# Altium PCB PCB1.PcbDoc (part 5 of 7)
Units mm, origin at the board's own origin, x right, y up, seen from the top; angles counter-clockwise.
Board outline 139.9 x 46.81 mm, 2 copper layers (Top Layer, Bottom Layer); 0 components, 100 nets, 100 pads, 0 vias.
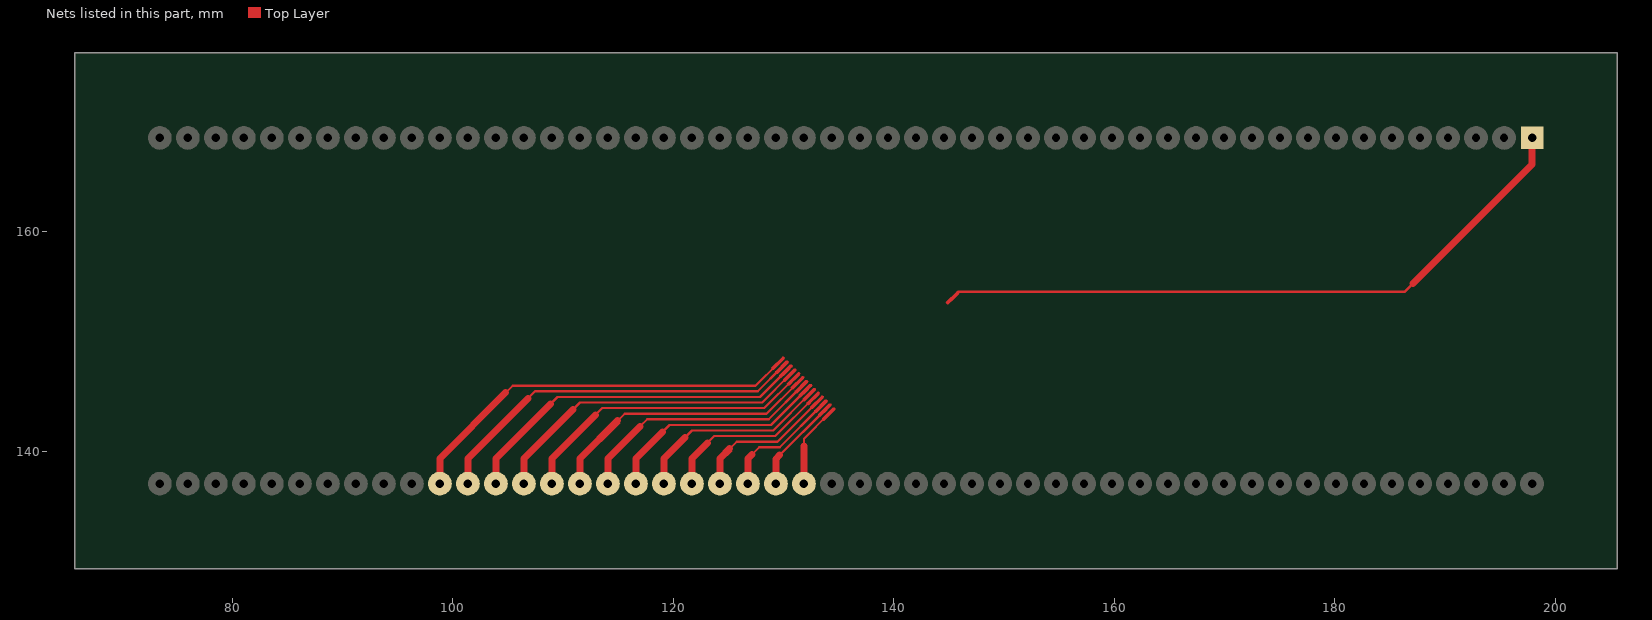
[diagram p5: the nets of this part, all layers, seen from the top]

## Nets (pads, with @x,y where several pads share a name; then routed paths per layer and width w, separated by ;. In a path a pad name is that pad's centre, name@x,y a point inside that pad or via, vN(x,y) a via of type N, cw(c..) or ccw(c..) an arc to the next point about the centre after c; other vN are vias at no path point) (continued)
$Net59: pad.1@197.885,168.455 | length 83.9
  Top Layer w0.03: 144.776,153.497 145.032,153.497 ; 144.776,153.512 145.047,153.512 ; 144.778,153.527 145.063,153.527 ; 144.781,153.481 145.017,153.481 ; 144.788,153.466 145.002,153.466 ; 144.799,153.451 144.987,153.451 ; 144.804,153.573 145.108,153.573 ; 144.811,153.436 144.971,153.436 ; 144.819,153.588 145.124,153.588 ; 144.826,153.42 144.956,153.42 ; 144.834,153.603 145.139,153.603 ; 144.849,153.405 144.938,153.405 ; 144.849,153.619 145.154,153.619 ; 144.865,153.634 145.169,153.634 ; 144.88,153.649 145.185,153.649 ; 144.895,153.664 145.2,153.664 ; 144.91,153.68 145.215,153.68 ; 144.926,153.695 145.23,153.695 ; 144.941,153.71 145.246,153.71 ; 144.956,153.725 145.261,153.725 ; 144.971,153.741 145.276,153.741 ; 144.987,153.756 145.291,153.756 ; 145.002,153.771 145.307,153.771 ; 145.017,153.786 145.322,153.786 ; 145.032,153.801 145.337,153.801 ; 145.047,153.817 145.352,153.817 ; 145.063,153.832 145.368,153.832 ; 145.078,153.542 144.781,153.542 ; 145.078,153.847 145.383,153.847 ; 145.093,153.558 144.788,153.558 ; 145.093,153.862 145.398,153.862 ; 145.108,153.878 145.416,153.878 ; 145.124,153.893 145.431,153.893 ; 145.139,153.908 145.446,153.908 ; 145.154,153.923 145.461,153.923 ; 145.169,153.939 145.477,153.939 ; 145.185,153.954 145.492,153.954 ; 145.2,153.969 145.507,153.969 ; 145.215,153.984 145.522,153.984 ; 145.23,154 145.538,154 ; 145.246,154.015 145.553,154.015 ; 145.261,154.03 145.568,154.03 ; 145.279,154.045 145.583,154.045 ; 145.294,154.061 145.599,154.061 ; 145.309,154.076 145.614,154.076 ; 145.324,154.091 145.629,154.091 ; 145.34,154.106 145.644,154.106 ; 145.355,154.122 145.66,154.122 ; 145.37,154.137 145.675,154.137 ; 145.385,154.152 145.69,154.152 ; 145.401,154.167 145.705,154.167 ; 145.416,154.182 145.721,154.182 ; 145.431,154.198 145.736,154.198 ; 145.446,154.213 145.751,154.213 ; 145.461,154.228 145.766,154.228 ; 145.477,154.243 145.782,154.243 ; 145.492,154.259 145.797,154.259 ; 145.507,154.274 145.812,154.274 ; 145.522,154.289 145.827,154.289 ; 145.538,154.304 145.842,154.304 ; 145.553,154.32 145.858,154.32 ; 145.568,154.335 145.873,154.335 ; 145.583,154.35 145.888,154.35 ; 145.599,154.365 145.898,154.365 ; 145.614,154.381 145.906,154.381 ; 145.629,154.396 145.909,154.396 ; 145.644,154.411 145.911,154.411 ; 145.66,154.426 145.909,154.426 ; 145.675,154.442 145.903,154.442 ; 145.69,154.457 145.893,154.457 ; 145.705,154.472 145.883,154.472 ; 145.721,154.487 145.868,154.487 ; 145.736,154.503 145.853,154.503 ; 145.756,154.518 145.83,154.518 ; 144.781,153.542 144.788,153.558 ; 144.781,153.542 144.773,153.509 144.776,153.492 144.781,153.476 144.801,153.446 144.829,153.418 144.86,153.398 144.875,153.393 144.893,153.39 144.926,153.398 144.938,153.405 ; 144.788,153.558 144.799,153.57 145.746,154.513 145.759,154.52 145.792,154.528 145.809,154.525 145.825,154.52 145.855,154.5 145.883,154.472 ; 144.938,153.405 145.886,154.348 145.896,154.36 145.903,154.376 145.911,154.409 145.909,154.426 ; 145.883,154.472 145.903,154.442 ; 145.903,154.442 145.909,154.426
  Top Layer w0.241: 145.342,153.959 145.868,154.485 186.328,154.485 187.09,155.247
  Top Layer w0.635: 187.09,155.247 187.217,155.374 197.885,166.042 pad.1@197.885,168.455
$Net60: pad.1@98.827,137.086 | length 60.5
  Top Layer w0.03: 128.939,147.556 129.195,147.556 ; 128.939,147.571 129.211,147.571 ; 128.941,147.586 129.226,147.586 ; 128.944,147.54 129.18,147.54 ; 128.951,147.525 129.165,147.525 ; 128.962,147.51 129.15,147.51 ; 128.967,147.632 129.272,147.632 ; 128.974,147.495 129.134,147.495 ; 128.982,147.647 129.287,147.647 ; 128.99,147.479 129.119,147.479 ; 128.997,147.662 129.302,147.662 ; 129.012,147.464 129.101,147.464 ; 129.012,147.678 129.317,147.678 ; 129.028,147.693 129.332,147.693 ; 129.043,147.708 129.348,147.708 ; 129.058,147.723 129.363,147.723 ; 129.073,147.739 129.378,147.739 ; 129.089,147.754 129.393,147.754 ; 129.104,147.769 129.409,147.769 ; 129.119,147.784 129.424,147.784 ; 129.134,147.799 129.439,147.799 ; 129.15,147.815 129.454,147.815 ; 129.165,147.83 129.47,147.83 ; 129.18,147.845 129.485,147.845 ; 129.195,147.86 129.5,147.86 ; 129.211,147.876 129.515,147.876 ; 129.226,147.891 129.531,147.891 ; 129.241,147.601 128.944,147.601 ; 129.241,147.906 129.546,147.906 ; 129.256,147.617 128.951,147.617 ; 129.256,147.921 129.561,147.921 ; 129.272,147.937 129.579,147.937 ; 129.287,147.952 129.594,147.952 ; 129.302,147.967 129.609,147.967 ; 129.317,147.982 129.625,147.982 ; 129.332,147.998 129.64,147.998 ; 129.348,148.013 129.655,148.013 ; 129.363,148.028 129.67,148.028 ; 129.378,148.043 129.686,148.043 ; 129.393,148.059 129.701,148.059 ; 129.409,148.074 129.716,148.074 ; 129.424,148.089 129.731,148.089 ; 129.442,148.104 129.747,148.104 ; 129.457,148.12 129.762,148.12 ; 129.472,148.135 129.777,148.135 ; 129.487,148.15 129.792,148.15 ; 129.503,148.165 129.807,148.165 ; 129.518,148.18 129.823,148.18 ; 129.533,148.196 129.838,148.196 ; 129.548,148.211 129.853,148.211 ; 129.564,148.226 129.868,148.226 ; 129.579,148.241 129.884,148.241 ; 129.594,148.257 129.899,148.257 ; 129.609,148.272 129.914,148.272 ; 129.625,148.287 129.929,148.287 ; 129.64,148.302 129.945,148.302 ; 129.655,148.318 129.96,148.318 ; 129.67,148.333 129.975,148.333 ; 129.686,148.348 129.99,148.348 ; 129.701,148.363 130.006,148.363 ; 129.716,148.379 130.021,148.379 ; 129.731,148.394 130.036,148.394 ; 129.747,148.409 130.051,148.409 ; 129.762,148.424 130.061,148.424 ; 129.777,148.44 130.069,148.44 ; 129.792,148.455 130.072,148.455 ; 129.807,148.47 130.074,148.47 ; 129.823,148.485 130.072,148.485 ; 129.838,148.501 130.067,148.501 ; 129.853,148.516 130.056,148.516 ; 129.868,148.531 130.046,148.531 ; 129.884,148.546 130.031,148.546 ; 129.899,148.561 130.016,148.561 ; 129.919,148.577 129.993,148.577 ; 128.944,147.601 128.951,147.617 ; 128.944,147.601 128.936,147.568 128.939,147.551 128.944,147.535 128.964,147.505 128.992,147.477 129.023,147.457 129.038,147.451 129.056,147.449 129.089,147.457 129.101,147.464 ; 128.951,147.617 128.962,147.629 129.909,148.572 129.922,148.579 129.955,148.587 129.973,148.584 129.988,148.579 130.018,148.559 130.046,148.531 ; 129.101,147.464 130.049,148.407 130.059,148.419 130.067,148.434 130.074,148.467 130.072,148.485 ; 130.046,148.531 130.067,148.501 ; 130.067,148.501 130.072,148.485
  Top Layer w0.203: 104.796,145.341 105.431,145.976 127.461,145.976 129.505,148.018
  Top Layer w0.635: pad.1@98.827,137.086 98.827,139.372 104.796,145.341
$Net61: pad.1@101.367,137.086 | length 58.1
  Top Layer w0.03: 129.292,147.203 129.548,147.203 ; 129.292,147.218 129.564,147.218 ; 129.294,147.233 129.579,147.233 ; 129.297,147.187 129.533,147.187 ; 129.305,147.172 129.518,147.172 ; 129.315,147.157 129.503,147.157 ; 129.32,147.279 129.625,147.279 ; 129.327,147.142 129.487,147.142 ; 129.335,147.294 129.64,147.294 ; 129.343,147.126 129.472,147.126 ; 129.35,147.309 129.655,147.309 ; 129.366,147.111 129.454,147.111 ; 129.366,147.324 129.67,147.324 ; 129.381,147.34 129.686,147.34 ; 129.396,147.355 129.701,147.355 ; 129.411,147.37 129.716,147.37 ; 129.426,147.385 129.731,147.385 ; 129.442,147.401 129.747,147.401 ; 129.457,147.416 129.762,147.416 ; 129.472,147.431 129.777,147.431 ; 129.487,147.446 129.792,147.446 ; 129.503,147.462 129.807,147.462 ; 129.518,147.477 129.823,147.477 ; 129.533,147.492 129.838,147.492 ; 129.548,147.507 129.853,147.507 ; 129.564,147.523 129.868,147.523 ; 129.579,147.538 129.884,147.538 ; 129.594,147.248 129.297,147.248 ; 129.594,147.553 129.899,147.553 ; 129.609,147.264 129.305,147.264 ; 129.609,147.568 129.914,147.568 ; 129.625,147.584 129.932,147.584 ; 129.64,147.599 129.947,147.599 ; 129.655,147.614 129.962,147.614 ; 129.67,147.629 129.978,147.629 ; 129.686,147.645 129.993,147.645 ; 129.701,147.66 130.008,147.66 ; 129.716,147.675 130.023,147.675 ; 129.731,147.69 130.039,147.69 ; 129.747,147.705 130.054,147.705 ; 129.762,147.721 130.069,147.721 ; 129.777,147.736 130.084,147.736 ; 129.795,147.751 130.1,147.751 ; 129.81,147.766 130.115,147.766 ; 129.825,147.782 130.13,147.782 ; 129.84,147.797 130.145,147.797 ; 129.856,147.812 130.161,147.812 ; 129.871,147.827 130.176,147.827 ; 129.886,147.843 130.191,147.843 ; 129.901,147.858 130.206,147.858 ; 129.917,147.873 130.221,147.873 ; 129.932,147.888 130.237,147.888 ; 129.947,147.904 130.252,147.904 ; 129.962,147.919 130.267,147.919 ; 129.978,147.934 130.282,147.934 ; 129.993,147.949 130.298,147.949 ; 130.008,147.965 130.313,147.965 ; 130.023,147.98 130.328,147.98 ; 130.039,147.995 130.343,147.995 ; 130.054,148.01 130.359,148.01 ; 130.069,148.026 130.374,148.026 ; 130.084,148.041 130.389,148.041 ; 130.1,148.056 130.404,148.056 ; 130.115,148.071 130.415,148.071 ; 130.13,148.086 130.422,148.086 ; 130.145,148.102 130.425,148.102 ; 130.161,148.117 130.427,148.117 ; 130.176,148.132 130.425,148.132 ; 130.191,148.147 130.42,148.147 ; 130.206,148.163 130.409,148.163 ; 130.221,148.178 130.399,148.178 ; 130.237,148.193 130.384,148.193 ; 130.252,148.208 130.369,148.208 ; 130.272,148.224 130.346,148.224 ; 129.297,147.248 129.305,147.264 ; 129.297,147.248 129.289,147.215 129.292,147.197 129.297,147.182 129.317,147.152 129.345,147.124 129.376,147.104 129.391,147.098 129.409,147.096 129.442,147.104 129.454,147.111 ; 129.305,147.264 129.315,147.276 130.262,148.219 130.275,148.226 130.308,148.234 130.326,148.231 130.341,148.226 130.371,148.206 130.399,148.178 ; 129.454,147.111 130.402,148.053 130.412,148.066 130.42,148.081 130.427,148.114 130.425,148.132 ; 130.399,148.178 130.42,148.147 ; 130.42,148.147 130.425,148.132
  Top Layer w0.203: 106.828,144.833 107.463,145.468 127.659,145.468 129.858,147.665
  Top Layer w0.635: pad.1@101.367,137.086 101.367,139.372 106.828,144.833
$Net62: pad.1@103.907,137.086 | length 55.8
  Top Layer w0.03: 129.645,146.85 129.901,146.85 ; 129.645,146.865 129.917,146.865 ; 129.647,146.88 129.932,146.88 ; 129.65,146.834 129.886,146.834 ; 129.658,146.819 129.871,146.819 ; 129.668,146.804 129.856,146.804 ; 129.673,146.926 129.978,146.926 ; 129.68,146.789 129.84,146.789 ; 129.688,146.941 129.993,146.941 ; 129.696,146.773 129.825,146.773 ; 129.703,146.956 130.008,146.956 ; 129.719,146.758 129.807,146.758 ; 129.719,146.971 130.023,146.971 ; 129.734,146.987 130.039,146.987 ; 129.749,147.002 130.054,147.002 ; 129.764,147.017 130.069,147.017 ; 129.78,147.032 130.084,147.032 ; 129.795,147.048 130.1,147.048 ; 129.81,147.063 130.115,147.063 ; 129.825,147.078 130.13,147.078 ; 129.84,147.093 130.145,147.093 ; 129.856,147.109 130.161,147.109 ; 129.871,147.124 130.176,147.124 ; 129.886,147.139 130.191,147.139 ; 129.901,147.154 130.206,147.154 ; 129.917,147.17 130.221,147.17 ; 129.932,147.185 130.237,147.185 ; 129.947,146.895 129.65,146.895 ; 129.947,147.2 130.252,147.2 ; 129.962,146.91 129.658,146.91 ; 129.962,147.215 130.267,147.215 ; 129.978,147.231 130.285,147.231 ; 129.993,147.246 130.3,147.246 ; 130.008,147.261 130.315,147.261 ; 130.023,147.276 130.331,147.276 ; 130.039,147.291 130.346,147.291 ; 130.054,147.307 130.361,147.307 ; 130.069,147.322 130.376,147.322 ; 130.084,147.337 130.392,147.337 ; 130.1,147.352 130.407,147.352 ; 130.115,147.368 130.422,147.368 ; 130.13,147.383 130.437,147.383 ; 130.148,147.398 130.453,147.398 ; 130.163,147.413 130.468,147.413 ; 130.178,147.429 130.483,147.429 ; 130.194,147.444 130.498,147.444 ; 130.209,147.459 130.514,147.459 ; 130.224,147.474 130.529,147.474 ; 130.239,147.49 130.544,147.49 ; 130.255,147.505 130.559,147.505 ; 130.27,147.52 130.575,147.52 ; 130.285,147.535 130.59,147.535 ; 130.3,147.551 130.605,147.551 ; 130.315,147.566 130.62,147.566 ; 130.331,147.581 130.636,147.581 ; 130.346,147.596 130.651,147.596 ; 130.361,147.612 130.666,147.612 ; 130.376,147.627 130.681,147.627 ; 130.392,147.642 130.696,147.642 ; 130.407,147.657 130.712,147.657 ; 130.422,147.672 130.727,147.672 ; 130.437,147.688 130.742,147.688 ; 130.453,147.703 130.757,147.703 ; 130.468,147.718 130.768,147.718 ; 130.483,147.733 130.775,147.733 ; 130.498,147.749 130.778,147.749 ; 130.514,147.764 130.78,147.764 ; 130.529,147.779 130.778,147.779 ; 130.544,147.794 130.773,147.794 ; 130.559,147.81 130.763,147.81 ; 130.575,147.825 130.752,147.825 ; 130.59,147.84 130.737,147.84 ; 130.605,147.855 130.722,147.855 ; 130.625,147.871 130.699,147.871 ; 129.65,146.895 129.658,146.91 ; 129.65,146.895 129.642,146.862 129.645,146.844 129.65,146.829 129.67,146.799 129.698,146.771 129.729,146.75 129.744,146.745 129.762,146.743 129.795,146.75 129.807,146.758 ; 129.658,146.91 129.668,146.923 130.615,147.866 130.628,147.873 130.661,147.881 130.679,147.878 130.694,147.873 130.724,147.853 130.752,147.825 ; 129.807,146.758 130.755,147.7 130.765,147.713 130.773,147.728 130.78,147.761 130.778,147.779 ; 130.752,147.825 130.773,147.794 ; 130.773,147.794 130.778,147.779
  Top Layer w0.203: 108.86,144.325 109.495,144.96 127.859,144.96 130.211,147.312
  Top Layer w0.635: pad.1@103.907,137.086 103.907,139.372 108.86,144.325
$Net63: pad.1@106.447,137.086 | length 53.5
  Top Layer w0.03: 129.998,146.496 130.255,146.496 ; 129.998,146.512 130.27,146.512 ; 130.001,146.527 130.285,146.527 ; 130.003,146.481 130.239,146.481 ; 130.011,146.466 130.224,146.466 ; 130.021,146.451 130.209,146.451 ; 130.026,146.573 130.331,146.573 ; 130.034,146.435 130.194,146.435 ; 130.041,146.588 130.346,146.588 ; 130.049,146.42 130.178,146.42 ; 130.056,146.603 130.361,146.603 ; 130.072,146.405 130.161,146.405 ; 130.072,146.618 130.376,146.618 ; 130.087,146.634 130.392,146.634 ; 130.102,146.649 130.407,146.649 ; 130.117,146.664 130.422,146.664 ; 130.133,146.679 130.437,146.679 ; 130.148,146.695 130.453,146.695 ; 130.163,146.71 130.468,146.71 ; 130.178,146.725 130.483,146.725 ; 130.194,146.74 130.498,146.74 ; 130.209,146.756 130.514,146.756 ; 130.224,146.771 130.529,146.771 ; 130.239,146.786 130.544,146.786 ; 130.255,146.801 130.559,146.801 ; 130.27,146.816 130.575,146.816 ; 130.285,146.832 130.59,146.832 ; 130.3,146.542 130.003,146.542 ; 130.3,146.847 130.605,146.847 ; 130.315,146.557 130.011,146.557 ; 130.315,146.862 130.62,146.862 ; 130.331,146.877 130.638,146.877 ; 130.346,146.893 130.653,146.893 ; 130.361,146.908 130.669,146.908 ; 130.376,146.923 130.684,146.923 ; 130.392,146.938 130.699,146.938 ; 130.407,146.954 130.714,146.954 ; 130.422,146.969 130.729,146.969 ; 130.437,146.984 130.745,146.984 ; 130.453,146.999 130.76,146.999 ; 130.468,147.015 130.775,147.015 ; 130.483,147.03 130.79,147.03 ; 130.501,147.045 130.806,147.045 ; 130.516,147.06 130.821,147.06 ; 130.531,147.076 130.836,147.076 ; 130.547,147.091 130.851,147.091 ; 130.562,147.106 130.867,147.106 ; 130.577,147.121 130.882,147.121 ; 130.592,147.137 130.897,147.137 ; 130.608,147.152 130.912,147.152 ; 130.623,147.167 130.928,147.167 ; 130.638,147.182 130.943,147.182 ; 130.653,147.197 130.958,147.197 ; 130.669,147.213 130.973,147.213 ; 130.684,147.228 130.989,147.228 ; 130.699,147.243 131.004,147.243 ; 130.714,147.258 131.019,147.258 ; 130.729,147.274 131.034,147.274 ; 130.745,147.289 131.05,147.289 ; 130.76,147.304 131.065,147.304 ; 130.775,147.319 131.08,147.319 ; 130.79,147.335 131.095,147.335 ; 130.806,147.35 131.11,147.35 ; 130.821,147.365 131.121,147.365 ; 130.836,147.38 131.128,147.38 ; 130.851,147.396 131.131,147.396 ; 130.867,147.411 131.133,147.411 ; 130.882,147.426 131.131,147.426 ; 130.897,147.441 131.126,147.441 ; 130.912,147.457 131.116,147.457 ; 130.928,147.472 131.105,147.472 ; 130.943,147.487 131.09,147.487 ; 130.958,147.502 131.075,147.502 ; 130.978,147.518 131.052,147.518 ; 130.003,146.542 130.011,146.557 ; 130.003,146.542 129.995,146.509 129.998,146.491 130.003,146.476 130.023,146.446 130.051,146.418 130.082,146.397 130.097,146.392 130.115,146.39 130.148,146.397 130.161,146.405 ; 130.011,146.557 130.021,146.57 130.968,147.512 130.981,147.52 131.014,147.528 131.032,147.525 131.047,147.52 131.077,147.5 131.105,147.472 ; 130.161,146.405 131.108,147.347 131.118,147.36 131.126,147.375 131.133,147.408 131.131,147.426 ; 131.105,147.472 131.126,147.441 ; 131.126,147.441 131.131,147.426
  Top Layer w0.203: 110.892,143.817 111.527,144.452 128.057,144.452 130.564,146.959
  Top Layer w0.635: pad.1@106.447,137.086 106.447,139.372 110.892,143.817
$Net64: pad.1@108.987,137.086 | length 51.1
  Top Layer w0.03: 130.351,146.143 130.608,146.143 ; 130.351,146.159 130.623,146.159 ; 130.354,146.174 130.638,146.174 ; 130.356,146.128 130.592,146.128 ; 130.364,146.113 130.577,146.113 ; 130.374,146.098 130.562,146.098 ; 130.379,146.22 130.684,146.22 ; 130.387,146.082 130.547,146.082 ; 130.394,146.235 130.699,146.235 ; 130.402,146.067 130.531,146.067 ; 130.409,146.25 130.714,146.25 ; 130.425,146.052 130.514,146.052 ; 130.425,146.265 130.729,146.265 ; 130.44,146.281 130.745,146.281 ; 130.455,146.296 130.76,146.296 ; 130.47,146.311 130.775,146.311 ; 130.486,146.326 130.79,146.326 ; 130.501,146.342 130.806,146.342 ; 130.516,146.357 130.821,146.357 ; 130.531,146.372 130.836,146.372 ; 130.547,146.387 130.851,146.387 ; 130.562,146.402 130.867,146.402 ; 130.577,146.418 130.882,146.418 ; 130.592,146.433 130.897,146.433 ; 130.608,146.448 130.912,146.448 ; 130.623,146.463 130.928,146.463 ; 130.638,146.479 130.943,146.479 ; 130.653,146.189 130.356,146.189 ; 130.653,146.494 130.958,146.494 ; 130.669,146.204 130.364,146.204 ; 130.669,146.509 130.973,146.509 ; 130.684,146.524 130.991,146.524 ; 130.699,146.54 131.006,146.54 ; 130.714,146.555 131.022,146.555 ; 130.729,146.57 131.037,146.57 ; 130.745,146.585 131.052,146.585 ; 130.76,146.601 131.067,146.601 ; 130.775,146.616 131.083,146.616 ; 130.79,146.631 131.098,146.631 ; 130.806,146.646 131.113,146.646 ; 130.821,146.662 131.128,146.662 ; 130.836,146.677 131.144,146.677 ; 130.854,146.692 131.159,146.692 ; 130.869,146.707 131.174,146.707 ; 130.884,146.723 131.189,146.723 ; 130.9,146.738 131.204,146.738 ; 130.915,146.753 131.22,146.753 ; 130.93,146.768 131.235,146.768 ; 130.945,146.783 131.25,146.783 ; 130.961,146.799 131.265,146.799 ; 130.976,146.814 131.281,146.814 ; 130.991,146.829 131.296,146.829 ; 131.006,146.844 131.311,146.844 ; 131.022,146.86 131.326,146.86 ; 131.037,146.875 131.342,146.875 ; 131.052,146.89 131.357,146.89 ; 131.067,146.905 131.372,146.905 ; 131.083,146.921 131.387,146.921 ; 131.098,146.936 131.403,146.936 ; 131.113,146.951 131.418,146.951 ; 131.128,146.966 131.433,146.966 ; 131.144,146.982 131.448,146.982 ; 131.159,146.997 131.464,146.997 ; 131.174,147.012 131.474,147.012 ; 131.189,147.027 131.481,147.027 ; 131.204,147.043 131.484,147.043 ; 131.22,147.058 131.486,147.058 ; 131.235,147.073 131.484,147.073 ; 131.25,147.088 131.479,147.088 ; 131.265,147.104 131.469,147.104 ; 131.281,147.119 131.458,147.119 ; 131.296,147.134 131.443,147.134 ; 131.311,147.149 131.428,147.149 ; 131.331,147.164 131.405,147.164 ; 130.356,146.189 130.364,146.204 ; 130.356,146.189 130.348,146.156 130.351,146.138 130.356,146.123 130.376,146.093 130.404,146.065 130.435,146.044 130.45,146.039 130.468,146.037 130.501,146.044 130.514,146.052 ; 130.364,146.204 130.374,146.217 131.321,147.159 131.334,147.167 131.367,147.175 131.385,147.172 131.4,147.167 131.431,147.147 131.458,147.119 ; 130.514,146.052 131.461,146.994 131.471,147.007 131.479,147.022 131.486,147.055 131.484,147.073 ; 131.458,147.119 131.479,147.088 ; 131.479,147.088 131.484,147.073
  Top Layer w0.203: 112.924,143.309 113.559,143.944 128.256,143.944 130.917,146.606
  Top Layer w0.635: pad.1@108.987,137.086 108.987,139.372 112.924,143.309
$Net65: pad.1@111.527,137.086 | length 48.8
  Top Layer w0.03: 130.707,145.79 130.963,145.79 ; 130.707,145.806 130.978,145.806 ; 130.709,145.821 130.994,145.821 ; 130.712,145.775 130.948,145.775 ; 130.719,145.76 130.933,145.76 ; 130.729,145.745 130.917,145.745 ; 130.735,145.867 131.039,145.867 ; 130.742,145.729 130.902,145.729 ; 130.75,145.882 131.055,145.882 ; 130.757,145.714 130.887,145.714 ; 130.765,145.897 131.07,145.897 ; 130.78,145.699 130.869,145.699 ; 130.78,145.912 131.085,145.912 ; 130.796,145.927 131.1,145.927 ; 130.811,145.943 131.116,145.943 ; 130.826,145.958 131.131,145.958 ; 130.841,145.973 131.146,145.973 ; 130.856,145.988 131.161,145.988 ; 130.872,146.004 131.177,146.004 ; 130.887,146.019 131.192,146.019 ; 130.902,146.034 131.207,146.034 ; 130.917,146.049 131.222,146.049 ; 130.933,146.065 131.237,146.065 ; 130.948,146.08 131.253,146.08 ; 130.963,146.095 131.268,146.095 ; 130.978,146.11 131.283,146.11 ; 130.994,146.126 131.298,146.126 ; 131.009,145.836 130.712,145.836 ; 131.009,146.141 131.314,146.141 ; 131.024,145.851 130.719,145.851 ; 131.024,146.156 131.329,146.156 ; 131.039,146.171 131.347,146.171 ; 131.055,146.187 131.362,146.187 ; 131.07,146.202 131.377,146.202 ; 131.085,146.217 131.392,146.217 ; 131.1,146.232 131.408,146.232 ; 131.116,146.248 131.423,146.248 ; 131.131,146.263 131.438,146.263 ; 131.146,146.278 131.453,146.278 ; 131.161,146.293 131.469,146.293 ; 131.177,146.308 131.484,146.308 ; 131.192,146.324 131.499,146.324 ; 131.21,146.339 131.514,146.339 ; 131.225,146.354 131.53,146.354 ; 131.24,146.369 131.545,146.369 ; 131.255,146.385 131.56,146.385 ; 131.271,146.4 131.575,146.4 ; 131.286,146.415 131.591,146.415 ; 131.301,146.43 131.606,146.43 ; 131.316,146.446 131.621,146.446 ; 131.331,146.461 131.636,146.461 ; 131.347,146.476 131.652,146.476 ; 131.362,146.491 131.667,146.491 ; 131.377,146.507 131.682,146.507 ; 131.392,146.522 131.697,146.522 ; 131.408,146.537 131.712,146.537 ; 131.423,146.552 131.728,146.552 ; 131.438,146.568 131.743,146.568 ; 131.453,146.583 131.758,146.583 ; 131.469,146.598 131.773,146.598 ; 131.484,146.613 131.789,146.613 ; 131.499,146.629 131.804,146.629 ; 131.514,146.644 131.819,146.644 ; 131.53,146.659 131.829,146.659 ; 131.545,146.674 131.837,146.674 ; 131.56,146.689 131.839,146.689 ; 131.575,146.705 131.842,146.705 ; 131.591,146.72 131.839,146.72 ; 131.606,146.735 131.834,146.735 ; 131.621,146.75 131.824,146.75 ; 131.636,146.766 131.814,146.766 ; 131.652,146.781 131.799,146.781 ; 131.667,146.796 131.784,146.796 ; 131.687,146.811 131.761,146.811 ; 130.712,145.836 130.719,145.851 ; 130.712,145.836 130.704,145.803 130.707,145.785 130.712,145.77 130.732,145.74 130.76,145.712 130.79,145.691 130.806,145.686 130.823,145.684 130.856,145.691 130.869,145.699 ; 130.719,145.851 130.729,145.864 131.677,146.806 131.69,146.814 131.723,146.822 131.74,146.819 131.756,146.814 131.786,146.794 131.814,146.766 ; 130.869,145.699 131.817,146.641 131.827,146.654 131.834,146.669 131.842,146.702 131.839,146.72 ; 131.814,146.766 131.834,146.735 ; 131.834,146.735 131.839,146.72
  Top Layer w0.203: 114.956,142.801 115.591,143.436 128.456,143.436 131.273,146.253
  Top Layer w0.635: pad.1@111.527,137.086 111.527,139.372 114.956,142.801
$Net66: pad.1@114.067,137.086 | length 46.5
  Top Layer w0.03: 131.06,145.435 131.316,145.435 ; 131.06,145.45 131.331,145.45 ; 131.062,145.465 131.347,145.465 ; 131.065,145.419 131.301,145.419 ; 131.072,145.404 131.286,145.404 ; 131.083,145.389 131.271,145.389 ; 131.088,145.511 131.392,145.511 ; 131.095,145.374 131.255,145.374 ; 131.103,145.526 131.408,145.526 ; 131.11,145.359 131.24,145.359 ; 131.118,145.541 131.423,145.541 ; 131.133,145.343 131.222,145.343 ; 131.133,145.557 131.438,145.557 ; 131.149,145.572 131.453,145.572 ; 131.164,145.587 131.469,145.587 ; 131.179,145.602 131.484,145.602 ; 131.194,145.618 131.499,145.618 ; 131.21,145.633 131.514,145.633 ; 131.225,145.648 131.53,145.648 ; 131.24,145.663 131.545,145.663 ; 131.255,145.679 131.56,145.679 ; 131.271,145.694 131.575,145.694 ; 131.286,145.709 131.591,145.709 ; 131.301,145.724 131.606,145.724 ; 131.316,145.74 131.621,145.74 ; 131.331,145.755 131.636,145.755 ; 131.347,145.77 131.652,145.77 ; 131.362,145.48 131.065,145.48 ; 131.362,145.785 131.667,145.785 ; 131.377,145.496 131.072,145.496 ; 131.377,145.8 131.682,145.8 ; 131.392,145.816 131.7,145.816 ; 131.408,145.831 131.715,145.831 ; 131.423,145.846 131.73,145.846 ; 131.438,145.861 131.745,145.861 ; 131.453,145.877 131.761,145.877 ; 131.469,145.892 131.776,145.892 ; 131.484,145.907 131.791,145.907 ; 131.499,145.922 131.806,145.922 ; 131.514,145.938 131.822,145.938 ; 131.53,145.953 131.837,145.953 ; 131.545,145.968 131.852,145.968 ; 131.563,145.983 131.867,145.983 ; 131.578,145.999 131.883,145.999 ; 131.593,146.014 131.898,146.014 ; 131.608,146.029 131.913,146.029 ; 131.624,146.044 131.928,146.044 ; 131.639,146.06 131.944,146.06 ; 131.654,146.075 131.959,146.075 ; 131.669,146.09 131.974,146.09 ; 131.685,146.105 131.989,146.105 ; 131.7,146.121 132.005,146.121 ; 131.715,146.136 132.02,146.136 ; 131.73,146.151 132.035,146.151 ; 131.745,146.166 132.05,146.166 ; 131.761,146.181 132.066,146.181 ; 131.776,146.197 132.081,146.197 ; 131.791,146.212 132.096,146.212 ; 131.806,146.227 132.111,146.227 ; 131.822,146.242 132.126,146.242 ; 131.837,146.258 132.142,146.258 ; 131.852,146.273 132.157,146.273 ; 131.867,146.288 132.172,146.288 ; 131.883,146.303 132.182,146.303 ; 131.898,146.319 132.19,146.319 ; 131.913,146.334 132.193,146.334 ; 131.928,146.349 132.195,146.349 ; 131.944,146.364 132.193,146.364 ; 131.959,146.38 132.187,146.38 ; 131.974,146.395 132.177,146.395 ; 131.989,146.41 132.167,146.41 ; 132.005,146.425 132.152,146.425 ; 132.02,146.441 132.137,146.441 ; 132.04,146.456 132.114,146.456 ; 131.065,145.48 131.072,145.496 ; 131.065,145.48 131.057,145.447 131.06,145.43 131.065,145.414 131.085,145.384 131.113,145.356 131.144,145.336 131.159,145.331 131.177,145.328 131.21,145.336 131.222,145.343 ; 131.072,145.496 131.083,145.508 132.03,146.451 132.043,146.458 132.076,146.466 132.093,146.463 132.109,146.458 132.139,146.438 132.167,146.41 ; 131.222,145.343 132.17,146.286 132.18,146.298 132.187,146.314 132.195,146.347 132.193,146.364 ; 132.167,146.41 132.187,146.38 ; 132.187,146.38 132.193,146.364
  Top Layer w0.203: 116.988,142.293 117.623,142.928 128.654,142.928 131.626,145.897
  Top Layer w0.635: pad.1@114.067,137.086 114.067,139.372 116.988,142.293
$Net67: pad.1@116.607,137.086 | length 44.1
  Top Layer w0.03: 131.413,145.082 131.669,145.082 ; 131.413,145.097 131.685,145.097 ; 131.415,145.112 131.7,145.112 ; 131.418,145.066 131.654,145.066 ; 131.425,145.051 131.639,145.051 ; 131.436,145.036 131.624,145.036 ; 131.441,145.158 131.745,145.158 ; 131.448,145.021 131.608,145.021 ; 131.456,145.173 131.761,145.173 ; 131.464,145.005 131.593,145.005 ; 131.471,145.188 131.776,145.188 ; 131.486,144.99 131.575,144.99 ; 131.486,145.204 131.791,145.204 ; 131.502,145.219 131.806,145.219 ; 131.517,145.234 131.822,145.234 ; 131.532,145.249 131.837,145.249 ; 131.547,145.265 131.852,145.265 ; 131.563,145.28 131.867,145.28 ; 131.578,145.295 131.883,145.295 ; 131.593,145.31 131.898,145.31 ; 131.608,145.326 131.913,145.326 ; 131.624,145.341 131.928,145.341 ; 131.639,145.356 131.944,145.356 ; 131.654,145.371 131.959,145.371 ; 131.669,145.386 131.974,145.386 ; 131.685,145.402 131.989,145.402 ; 131.7,145.417 132.005,145.417 ; 131.715,145.127 131.418,145.127 ; 131.715,145.432 132.02,145.432 ; 131.73,145.143 131.425,145.143 ; 131.73,145.447 132.035,145.447 ; 131.745,145.463 132.053,145.463 ; 131.761,145.478 132.068,145.478 ; 131.776,145.493 132.083,145.493 ; 131.791,145.508 132.099,145.508 ; 131.806,145.524 132.114,145.524 ; 131.822,145.539 132.129,145.539 ; 131.837,145.554 132.144,145.554 ; 131.852,145.569 132.16,145.569 ; 131.867,145.585 132.175,145.585 ; 131.883,145.6 132.19,145.6 ; 131.898,145.615 132.205,145.615 ; 131.916,145.63 132.22,145.63 ; 131.931,145.646 132.236,145.646 ; 131.946,145.661 132.251,145.661 ; 131.961,145.676 132.266,145.676 ; 131.977,145.691 132.281,145.691 ; 131.992,145.707 132.297,145.707 ; 132.007,145.722 132.312,145.722 ; 132.022,145.737 132.327,145.737 ; 132.038,145.752 132.342,145.752 ; 132.053,145.767 132.358,145.767 ; 132.068,145.783 132.373,145.783 ; 132.083,145.798 132.388,145.798 ; 132.099,145.813 132.403,145.813 ; 132.114,145.828 132.419,145.828 ; 132.129,145.844 132.434,145.844 ; 132.144,145.859 132.449,145.859 ; 132.16,145.874 132.464,145.874 ; 132.175,145.889 132.48,145.889 ; 132.19,145.905 132.495,145.905 ; 132.205,145.92 132.51,145.92 ; 132.22,145.935 132.525,145.935 ; 132.236,145.95 132.535,145.95 ; 132.251,145.966 132.543,145.966 ; 132.266,145.981 132.546,145.981 ; 132.281,145.996 132.548,145.996 ; 132.297,146.011 132.546,146.011 ; 132.312,146.027 132.541,146.027 ; 132.327,146.042 132.53,146.042 ; 132.342,146.057 132.52,146.057 ; 132.358,146.072 132.505,146.072 ; 132.373,146.088 132.49,146.088 ; 132.393,146.103 132.467,146.103 ; 131.418,145.127 131.425,145.143 ; 131.418,145.127 131.41,145.094 131.413,145.077 131.418,145.061 131.438,145.031 131.466,145.003 131.497,144.983 131.512,144.978 131.53,144.975 131.563,144.983 131.575,144.99 ; 131.425,145.143 131.436,145.155 132.383,146.098 132.396,146.105 132.429,146.113 132.447,146.11 132.462,146.105 132.492,146.085 132.52,146.057 ; 131.575,144.99 132.523,145.933 132.533,145.945 132.541,145.961 132.548,145.994 132.546,146.011 ; 132.52,146.057 132.541,146.027 ; 132.541,146.027 132.546,146.011
  Top Layer w0.203: 119.02,141.785 119.655,142.42 128.852,142.42 131.979,145.544
  Top Layer w0.635: pad.1@116.607,137.086 116.607,139.372 119.02,141.785
$Net68: pad.1@119.147,137.086 | length 41.8
  Top Layer w0.03: 131.766,144.729 132.022,144.729 ; 131.766,144.744 132.038,144.744 ; 131.768,144.759 132.053,144.759 ; 131.771,144.713 132.007,144.713 ; 131.779,144.698 131.992,144.698 ; 131.789,144.683 131.977,144.683 ; 131.794,144.805 132.099,144.805 ; 131.801,144.668 131.961,144.668 ; 131.809,144.82 132.114,144.82 ; 131.817,144.652 131.946,144.652 ; 131.824,144.835 132.129,144.835 ; 131.839,144.637 131.928,144.637 ; 131.839,144.851 132.144,144.851 ; 131.855,144.866 132.16,144.866 ; 131.87,144.881 132.175,144.881 ; 131.885,144.896 132.19,144.896 ; 131.9,144.911 132.205,144.911 ; 131.916,144.927 132.22,144.927 ; 131.931,144.942 132.236,144.942 ; 131.946,144.957 132.251,144.957 ; 131.961,144.972 132.266,144.972 ; 131.977,144.988 132.281,144.988 ; 131.992,145.003 132.297,145.003 ; 132.007,145.018 132.312,145.018 ; 132.022,145.033 132.327,145.033 ; 132.038,145.049 132.342,145.049 ; 132.053,145.064 132.358,145.064 ; 132.068,144.774 131.771,144.774 ; 132.068,145.079 132.373,145.079 ; 132.083,144.79 131.779,144.79 ; 132.083,145.094 132.388,145.094 ; 132.099,145.11 132.406,145.11 ; 132.114,145.125 132.421,145.125 ; 132.129,145.14 132.436,145.14 ; 132.144,145.155 132.452,145.155 ; 132.16,145.171 132.467,145.171 ; 132.175,145.186 132.482,145.186 ; 132.19,145.201 132.497,145.201 ; 132.205,145.216 132.513,145.216 ; 132.22,145.232 132.528,145.232 ; 132.236,145.247 132.543,145.247 ; 132.251,145.262 132.558,145.262 ; 132.269,145.277 132.574,145.277 ; 132.284,145.292 132.589,145.292 ; 132.299,145.308 132.604,145.308 ; 132.314,145.323 132.619,145.323 ; 132.33,145.338 132.634,145.338 ; 132.345,145.353 132.65,145.353 ; 132.36,145.369 132.665,145.369 ; 132.375,145.384 132.68,145.384 ; 132.391,145.399 132.695,145.399 ; 132.406,145.414 132.711,145.414 ; 132.421,145.43 132.726,145.43 ; 132.436,145.445 132.741,145.445 ; 132.452,145.46 132.756,145.46 ; 132.467,145.475 132.772,145.475 ; 132.482,145.491 132.787,145.491 ; 132.497,145.506 132.802,145.506 ; 132.513,145.521 132.817,145.521 ; 132.528,145.536 132.833,145.536 ; 132.543,145.552 132.848,145.552 ; 132.558,145.567 132.863,145.567 ; 132.574,145.582 132.878,145.582 ; 132.589,145.597 132.888,145.597 ; 132.604,145.613 132.896,145.613 ; 132.619,145.628 132.899,145.628 ; 132.634,145.643 132.901,145.643 ; 132.65,145.658 132.899,145.658 ; 132.665,145.673 132.894,145.673 ; 132.68,145.689 132.883,145.689 ; 132.695,145.704 132.873,145.704 ; 132.711,145.719 132.858,145.719 ; 132.726,145.734 132.843,145.734 ; 132.746,145.75 132.82,145.75 ; 131.771,144.774 131.779,144.79 ; 131.771,144.774 131.763,144.741 131.766,144.724 131.771,144.708 131.791,144.678 131.819,144.65 131.85,144.63 131.865,144.624 131.883,144.622 131.916,144.63 131.928,144.637 ; 131.779,144.79 131.789,144.802 132.736,145.745 132.749,145.752 132.782,145.76 132.8,145.757 132.815,145.752 132.845,145.732 132.873,145.704 ; 131.928,144.637 132.876,145.58 132.886,145.592 132.894,145.607 132.901,145.64 132.899,145.658 ; 132.873,145.704 132.894,145.673 ; 132.894,145.673 132.899,145.658
  Top Layer w0.203: 121.052,141.277 121.687,141.912 129.053,141.912 132.332,145.191
  Top Layer w0.635: pad.1@119.147,137.086 119.147,139.372 121.052,141.277
$Net69: pad.1@121.687,137.086 | length 39.5
  Top Layer w0.03: 132.119,144.376 132.375,144.376 ; 132.119,144.391 132.391,144.391 ; 132.121,144.406 132.406,144.406 ; 132.124,144.36 132.36,144.36 ; 132.132,144.345 132.345,144.345 ; 132.142,144.33 132.33,144.33 ; 132.147,144.452 132.452,144.452 ; 132.154,144.315 132.314,144.315 ; 132.162,144.467 132.467,144.467 ; 132.17,144.299 132.299,144.299 ; 132.177,144.482 132.482,144.482 ; 132.193,144.284 132.281,144.284 ; 132.193,144.497 132.497,144.497 ; 132.208,144.513 132.513,144.513 ; 132.223,144.528 132.528,144.528 ; 132.238,144.543 132.543,144.543 ; 132.253,144.558 132.558,144.558 ; 132.269,144.574 132.574,144.574 ; 132.284,144.589 132.589,144.589 ; 132.299,144.604 132.604,144.604 ; 132.314,144.619 132.619,144.619 ; 132.33,144.635 132.634,144.635 ; 132.345,144.65 132.65,144.65 ; 132.36,144.665 132.665,144.665 ; 132.375,144.68 132.68,144.68 ; 132.391,144.696 132.695,144.696 ; 132.406,144.711 132.711,144.711 ; 132.421,144.421 132.124,144.421 ; 132.421,144.726 132.726,144.726 ; 132.436,144.437 132.132,144.437 ; 132.436,144.741 132.741,144.741 ; 132.452,144.757 132.759,144.757 ; 132.467,144.772 132.774,144.772 ; 132.482,144.787 132.789,144.787 ; 132.497,144.802 132.805,144.802 ; 132.513,144.818 132.82,144.818 ; 132.528,144.833 132.835,144.833 ; 132.543,144.848 132.85,144.848 ; 132.558,144.863 132.866,144.863 ; 132.574,144.878 132.881,144.878 ; 132.589,144.894 132.896,144.894 ; 132.604,144.909 132.911,144.909 ; 132.622,144.924 132.927,144.924 ; 132.637,144.939 132.942,144.939 ; 132.652,144.955 132.957,144.955 ; 132.668,144.97 132.972,144.97 ; 132.683,144.985 132.988,144.985 ; 132.698,145 133.003,145 ; 132.713,145.016 133.018,145.016 ; 132.728,145.031 133.033,145.031 ; 132.744,145.046 133.049,145.046 ; 132.759,145.061 133.064,145.061 ; 132.774,145.077 133.079,145.077 ; 132.789,145.092 133.094,145.092 ; 132.805,145.107 133.109,145.107 ; 132.82,145.122 133.125,145.122 ; 132.835,145.138 133.14,145.138 ; 132.85,145.153 133.155,145.153 ; 132.866,145.168 133.17,145.168 ; 132.881,145.183 133.186,145.183 ; 132.896,145.199 133.201,145.199 ; 132.911,145.214 133.216,145.214 ; 132.927,145.229 133.231,145.229 ; 132.942,145.244 133.242,145.244 ; 132.957,145.259 133.249,145.259 ; 132.972,145.275 133.252,145.275 ; 132.988,145.29 133.254,145.29 ; 133.003,145.305 133.252,145.305 ; 133.018,145.32 133.247,145.32 ; 133.033,145.336 133.236,145.336 ; 133.049,145.351 133.226,145.351 ; 133.064,145.366 133.211,145.366 ; 133.079,145.381 133.196,145.381 ; 133.099,145.397 133.173,145.397 ; 132.124,144.421 132.132,144.437 ; 132.124,144.421 132.116,144.388 132.119,144.37 132.124,144.355 132.144,144.325 132.172,144.297 132.203,144.276 132.218,144.271 132.236,144.269 132.269,144.276 132.281,144.284 ; 132.132,144.437 132.142,144.449 133.089,145.392 133.102,145.399 133.135,145.407 133.153,145.404 133.168,145.399 133.198,145.379 133.226,145.351 ; 132.281,144.284 133.229,145.226 133.239,145.239 133.247,145.254 133.254,145.287 133.252,145.305 ; 133.226,145.351 133.247,145.32 ; 133.247,145.32 133.252,145.305
  Top Layer w0.203: 123.084,140.769 123.719,141.404 129.251,141.404 132.685,144.838
  Top Layer w0.635: pad.1@121.687,137.086 121.687,139.372 123.084,140.769
$Net70: pad.1@124.227,137.086 | length 37.1
  Top Layer w0.03: 132.472,144.022 132.728,144.022 ; 132.472,144.038 132.744,144.038 ; 132.474,144.053 132.759,144.053 ; 132.477,144.007 132.713,144.007 ; 132.485,143.992 132.698,143.992 ; 132.495,143.977 132.683,143.977 ; 132.5,144.099 132.805,144.099 ; 132.507,143.962 132.668,143.962 ; 132.515,144.114 132.82,144.114 ; 132.523,143.946 132.652,143.946 ; 132.53,144.129 132.835,144.129 ; 132.546,143.931 132.634,143.931 ; 132.546,144.144 132.85,144.144 ; 132.561,144.16 132.866,144.16 ; 132.576,144.175 132.881,144.175 ; 132.591,144.19 132.896,144.19 ; 132.607,144.205 132.911,144.205 ; 132.622,144.221 132.927,144.221 ; 132.637,144.236 132.942,144.236 ; 132.652,144.251 132.957,144.251 ; 132.668,144.266 132.972,144.266 ; 132.683,144.282 132.988,144.282 ; 132.698,144.297 133.003,144.297 ; 132.713,144.312 133.018,144.312 ; 132.728,144.327 133.033,144.327 ; 132.744,144.343 133.049,144.343 ; 132.759,144.358 133.064,144.358 ; 132.774,144.068 132.477,144.068 ; 132.774,144.373 133.079,144.373 ; 132.789,144.083 132.485,144.083 ; 132.789,144.388 133.094,144.388 ; 132.805,144.403 133.112,144.403 ; 132.82,144.419 133.127,144.419 ; 132.835,144.434 133.142,144.434 ; 132.85,144.449 133.158,144.449 ; 132.866,144.464 133.173,144.464 ; 132.881,144.48 133.188,144.48 ; 132.896,144.495 133.203,144.495 ; 132.911,144.51 133.219,144.51 ; 132.927,144.525 133.234,144.525 ; 132.942,144.541 133.249,144.541 ; 132.957,144.556 133.264,144.556 ; 132.975,144.571 133.28,144.571 ; 132.99,144.586 133.295,144.586 ; 133.005,144.602 133.31,144.602 ; 133.021,144.617 133.325,144.617 ; 133.036,144.632 133.341,144.632 ; 133.051,144.647 133.356,144.647 ; 133.066,144.663 133.371,144.663 ; 133.082,144.678 133.386,144.678 ; 133.097,144.693 133.402,144.693 ; 133.112,144.708 133.417,144.708 ; 133.127,144.724 133.432,144.724 ; 133.142,144.739 133.447,144.739 ; 133.158,144.754 133.463,144.754 ; 133.173,144.769 133.478,144.769 ; 133.188,144.784 133.493,144.784 ; 133.203,144.8 133.508,144.8 ; 133.219,144.815 133.523,144.815 ; 133.234,144.83 133.539,144.83 ; 133.249,144.845 133.554,144.845 ; 133.264,144.861 133.569,144.861 ; 133.28,144.876 133.584,144.876 ; 133.295,144.891 133.595,144.891 ; 133.31,144.906 133.602,144.906 ; 133.325,144.922 133.605,144.922 ; 133.341,144.937 133.607,144.937 ; 133.356,144.952 133.605,144.952 ; 133.371,144.967 133.6,144.967 ; 133.386,144.983 133.59,144.983 ; 133.402,144.998 133.579,144.998 ; 133.417,145.013 133.564,145.013 ; 133.432,145.028 133.549,145.028 ; 133.452,145.044 133.526,145.044 ; 132.477,144.068 132.485,144.083 ; 132.477,144.068 132.469,144.035 132.472,144.017 132.477,144.002 132.497,143.972 132.525,143.944 132.556,143.923 132.571,143.918 132.589,143.916 132.622,143.923 132.634,143.931 ; 132.485,144.083 132.495,144.096 133.442,145.038 133.455,145.046 133.488,145.054 133.506,145.051 133.521,145.046 133.551,145.026 133.579,144.998 ; 132.634,143.931 133.582,144.873 133.592,144.886 133.6,144.901 133.607,144.934 133.605,144.952 ; 133.579,144.998 133.6,144.967 ; 133.6,144.967 133.605,144.952
  Top Layer w0.203: 125.116,140.261 125.751,140.896 129.452,140.896 133.038,144.485
  Top Layer w0.635: pad.1@124.227,137.086 124.227,139.372 125.116,140.261
$Net71: pad.1@126.767,137.086 | length 34.8
  Top Layer w0.03: 132.828,143.667 133.084,143.667 ; 132.828,143.682 133.099,143.682 ; 132.83,143.697 133.115,143.697 ; 132.833,143.652 133.069,143.652 ; 132.84,143.636 133.054,143.636 ; 132.85,143.621 133.038,143.621 ; 132.855,143.743 133.16,143.743 ; 132.863,143.606 133.023,143.606 ; 132.871,143.758 133.176,143.758 ; 132.878,143.591 133.008,143.591 ; 132.886,143.774 133.191,143.774 ; 132.901,143.575 132.99,143.575 ; 132.901,143.789 133.206,143.789 ; 132.916,143.804 133.221,143.804 ; 132.932,143.819 133.236,143.819 ; 132.947,143.835 133.252,143.835 ; 132.962,143.85 133.267,143.85 ; 132.977,143.865 133.282,143.865 ; 132.993,143.88 133.297,143.88 ; 133.008,143.895 133.313,143.895 ; 133.023,143.911 133.328,143.911 ; 133.038,143.926 133.343,143.926 ; 133.054,143.941 133.358,143.941 ; 133.069,143.956 133.374,143.956 ; 133.084,143.972 133.389,143.972 ; 133.099,143.987 133.404,143.987 ; 133.115,144.002 133.419,144.002 ; 133.13,143.713 132.833,143.713 ; 133.13,144.017 133.435,144.017 ; 133.145,143.728 132.84,143.728 ; 133.145,144.033 133.45,144.033 ; 133.16,144.048 133.468,144.048 ; 133.176,144.063 133.483,144.063 ; 133.191,144.078 133.498,144.078 ; 133.206,144.094 133.513,144.094 ; 133.221,144.109 133.529,144.109 ; 133.236,144.124 133.544,144.124 ; 133.252,144.139 133.559,144.139 ; 133.267,144.155 133.574,144.155 ; 133.282,144.17 133.59,144.17 ; 133.297,144.185 133.605,144.185 ; 133.313,144.2 133.62,144.2 ; 133.33,144.216 133.635,144.216 ; 133.346,144.231 133.65,144.231 ; 133.361,144.246 133.666,144.246 ; 133.376,144.261 133.681,144.261 ; 133.391,144.276 133.696,144.276 ; 133.407,144.292 133.711,144.292 ; 133.422,144.307 133.727,144.307 ; 133.437,144.322 133.742,144.322 ; 133.452,144.337 133.757,144.337 ; 133.468,144.353 133.772,144.353 ; 133.483,144.368 133.788,144.368 ; 133.498,144.383 133.803,144.383 ; 133.513,144.398 133.818,144.398 ; 133.529,144.414 133.833,144.414 ; 133.544,144.429 133.849,144.429 ; 133.559,144.444 133.864,144.444 ; 133.574,144.459 133.879,144.459 ; 133.59,144.475 133.894,144.475 ; 133.605,144.49 133.91,144.49 ; 133.62,144.505 133.925,144.505 ; 133.635,144.52 133.94,144.52 ; 133.65,144.536 133.95,144.536 ; 133.666,144.551 133.958,144.551 ; 133.681,144.566 133.96,144.566 ; 133.696,144.581 133.963,144.581 ; 133.711,144.597 133.96,144.597 ; 133.727,144.612 133.955,144.612 ; 133.742,144.627 133.945,144.627 ; 133.757,144.642 133.935,144.642 ; 133.772,144.657 133.92,144.657 ; 133.788,144.673 133.904,144.673 ; 133.808,144.688 133.882,144.688 ; 132.833,143.713 132.84,143.728 ; 132.833,143.713 132.825,143.68 132.828,143.662 132.833,143.647 132.853,143.616 132.881,143.588 132.911,143.568 132.927,143.563 132.944,143.56 132.977,143.568 132.99,143.575 ; 132.84,143.728 132.85,143.741 133.798,144.683 133.811,144.691 133.844,144.698 133.861,144.696 133.877,144.691 133.907,144.67 133.935,144.642 ; 132.99,143.575 133.938,144.518 133.948,144.53 133.955,144.546 133.963,144.579 133.96,144.597 ; 133.935,144.642 133.955,144.612 ; 133.955,144.612 133.96,144.597
  Top Layer w0.203: 127.148,139.753 127.783,140.388 129.65,140.388 133.394,144.129
  Top Layer w0.635: pad.1@126.767,137.086 126.767,139.372 127.148,139.753
$Net72: pad.1@129.307,137.086 | length 32.4
  Top Layer w0.03: 133.181,143.314 133.437,143.314 ; 133.181,143.329 133.452,143.329 ; 133.183,143.344 133.468,143.344 ; 133.186,143.299 133.422,143.299 ; 133.193,143.283 133.407,143.283 ; 133.203,143.268 133.391,143.268 ; 133.209,143.39 133.513,143.39 ; 133.216,143.253 133.376,143.253 ; 133.224,143.405 133.529,143.405 ; 133.231,143.238 133.361,143.238 ; 133.239,143.421 133.544,143.421 ; 133.254,143.222 133.343,143.222 ; 133.254,143.436 133.559,143.436 ; 133.269,143.451 133.574,143.451 ; 133.285,143.466 133.59,143.466 ; 133.3,143.481 133.605,143.481 ; 133.315,143.497 133.62,143.497 ; 133.33,143.512 133.635,143.512 ; 133.346,143.527 133.65,143.527 ; 133.361,143.542 133.666,143.542 ; 133.376,143.558 133.681,143.558 ; 133.391,143.573 133.696,143.573 ; 133.407,143.588 133.711,143.588 ; 133.422,143.603 133.727,143.603 ; 133.437,143.619 133.742,143.619 ; 133.452,143.634 133.757,143.634 ; 133.468,143.649 133.772,143.649 ; 133.483,143.36 133.186,143.36 ; 133.483,143.664 133.788,143.664 ; 133.498,143.375 133.193,143.375 ; 133.498,143.68 133.803,143.68 ; 133.513,143.695 133.821,143.695 ; 133.529,143.71 133.836,143.71 ; 133.544,143.725 133.851,143.725 ; 133.559,143.741 133.866,143.741 ; 133.574,143.756 133.882,143.756 ; 133.59,143.771 133.897,143.771 ; 133.605,143.786 133.912,143.786 ; 133.62,143.802 133.927,143.802 ; 133.635,143.817 133.943,143.817 ; 133.65,143.832 133.958,143.832 ; 133.666,143.847 133.973,143.847 ; 133.684,143.862 133.988,143.862 ; 133.699,143.878 134.004,143.878 ; 133.714,143.893 134.019,143.893 ; 133.729,143.908 134.034,143.908 ; 133.744,143.923 134.049,143.923 ; 133.76,143.939 134.065,143.939 ; 133.775,143.954 134.08,143.954 ; 133.79,143.969 134.095,143.969 ; 133.805,143.984 134.11,143.984 ; 133.821,144 134.125,144 ; 133.836,144.015 134.141,144.015 ; 133.851,144.03 134.156,144.03 ; 133.866,144.045 134.171,144.045 ; 133.882,144.061 134.186,144.061 ; 133.897,144.076 134.202,144.076 ; 133.912,144.091 134.217,144.091 ; 133.927,144.106 134.232,144.106 ; 133.943,144.122 134.247,144.122 ; 133.958,144.137 134.263,144.137 ; 133.973,144.152 134.278,144.152 ; 133.988,144.167 134.293,144.167 ; 134.004,144.183 134.303,144.183 ; 134.019,144.198 134.311,144.198 ; 134.034,144.213 134.313,144.213 ; 134.049,144.228 134.316,144.228 ; 134.065,144.243 134.313,144.243 ; 134.08,144.259 134.308,144.259 ; 134.095,144.274 134.298,144.274 ; 134.11,144.289 134.288,144.289 ; 134.125,144.304 134.273,144.304 ; 134.141,144.32 134.258,144.32 ; 134.161,144.335 134.235,144.335 ; 133.186,143.36 133.193,143.375 ; 133.186,143.36 133.178,143.327 133.181,143.309 133.186,143.294 133.206,143.263 133.234,143.235 133.264,143.215 133.28,143.21 133.297,143.207 133.33,143.215 133.343,143.222 ; 133.193,143.375 133.203,143.387 134.151,144.33 134.164,144.337 134.197,144.345 134.214,144.343 134.23,144.337 134.26,144.317 134.288,144.289 ; 133.343,143.222 134.291,144.165 134.301,144.177 134.308,144.193 134.316,144.226 134.313,144.243 ; 134.288,144.289 134.308,144.259 ; 134.308,144.259 134.313,144.243
  Top Layer w0.203: 129.64,139.671 133.747,143.776
  Top Layer w0.635: pad.1@129.307,137.086 129.307,139.336 129.64,139.671
$Net73: pad.1@131.847,137.086 | length 31.2
  Top Layer w0.03: 133.534,142.961 133.79,142.961 ; 133.534,142.976 133.805,142.976 ; 133.536,142.991 133.821,142.991 ; 133.539,142.946 133.775,142.946 ; 133.546,142.93 133.76,142.93 ; 133.557,142.915 133.744,142.915 ; 133.562,143.037 133.866,143.037 ; 133.569,142.9 133.729,142.9 ; 133.577,143.052 133.882,143.052 ; 133.584,142.885 133.714,142.885 ; 133.592,143.067 133.897,143.067 ; 133.607,142.869 133.696,142.869 ; 133.607,143.083 133.912,143.083 ; 133.623,143.098 133.927,143.098 ; 133.638,143.113 133.943,143.113 ; 133.653,143.128 133.958,143.128 ; 133.668,143.144 133.973,143.144 ; 133.684,143.159 133.988,143.159 ; 133.699,143.174 134.004,143.174 ; 133.714,143.189 134.019,143.189 ; 133.729,143.205 134.034,143.205 ; 133.744,143.22 134.049,143.22 ; 133.76,143.235 134.065,143.235 ; 133.775,143.25 134.08,143.25 ; 133.79,143.266 134.095,143.266 ; 133.805,143.281 134.11,143.281 ; 133.821,143.296 134.125,143.296 ; 133.836,143.006 133.539,143.006 ; 133.836,143.311 134.141,143.311 ; 133.851,143.022 133.546,143.022 ; 133.851,143.327 134.156,143.327 ; 133.866,143.342 134.174,143.342 ; 133.882,143.357 134.189,143.357 ; 133.897,143.372 134.204,143.372 ; 133.912,143.387 134.219,143.387 ; 133.927,143.403 134.235,143.403 ; 133.943,143.418 134.25,143.418 ; 133.958,143.433 134.265,143.433 ; 133.973,143.448 134.28,143.448 ; 133.988,143.464 134.296,143.464 ; 134.004,143.479 134.311,143.479 ; 134.019,143.494 134.326,143.494 ; 134.037,143.509 134.341,143.509 ; 134.052,143.525 134.357,143.525 ; 134.067,143.54 134.372,143.54 ; 134.082,143.555 134.387,143.555 ; 134.098,143.57 134.402,143.57 ; 134.113,143.586 134.418,143.586 ; 134.128,143.601 134.433,143.601 ; 134.143,143.616 134.448,143.616 ; 134.158,143.631 134.463,143.631 ; 134.174,143.647 134.479,143.647 ; 134.189,143.662 134.494,143.662 ; 134.204,143.677 134.509,143.677 ; 134.219,143.692 134.524,143.692 ; 134.235,143.708 134.539,143.708 ; 134.25,143.723 134.555,143.723 ; 134.265,143.738 134.57,143.738 ; 134.28,143.753 134.585,143.753 ; 134.296,143.768 134.6,143.768 ; 134.311,143.784 134.616,143.784 ; 134.326,143.799 134.631,143.799 ; 134.341,143.814 134.646,143.814 ; 134.357,143.829 134.656,143.829 ; 134.372,143.845 134.664,143.845 ; 134.387,143.86 134.666,143.86 ; 134.402,143.875 134.669,143.875 ; 134.418,143.89 134.666,143.89 ; 134.433,143.906 134.661,143.906 ; 134.448,143.921 134.651,143.921 ; 134.463,143.936 134.641,143.936 ; 134.479,143.951 134.626,143.951 ; 134.494,143.967 134.611,143.967 ; 134.514,143.982 134.588,143.982 ; 133.539,143.006 133.546,143.022 ; 133.539,143.006 133.531,142.973 133.534,142.956 133.539,142.94 133.559,142.91 133.587,142.882 133.617,142.862 133.633,142.857 133.65,142.854 133.684,142.862 133.696,142.869 ; 133.546,143.022 133.557,143.034 134.504,143.977 134.517,143.984 134.55,143.992 134.567,143.989 134.583,143.984 134.613,143.964 134.641,143.936 ; 133.696,142.869 134.644,143.812 134.654,143.824 134.661,143.84 134.669,143.873 134.666,143.89 ; 134.641,143.936 134.661,143.906 ; 134.661,143.906 134.666,143.89
  Top Layer w0.203: 131.847,140.515 131.847,141.168 134.1,143.423
  Top Layer w0.635: pad.1@131.847,137.086 131.847,140.515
